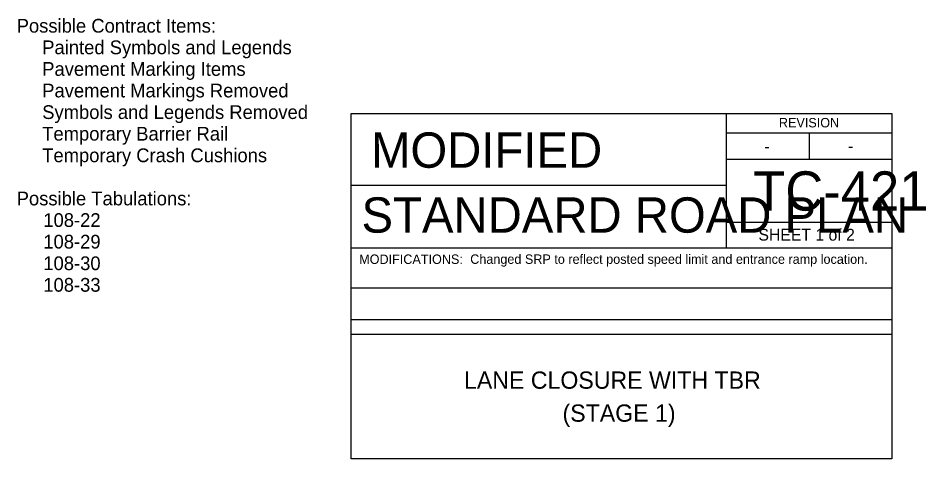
# Model space of a CAD drawing. Extents: x 10134 to 13311, y 7934 to 9733.
# Drawn here: x 12156 to 13311, y 7934 to 8495 of the extents above; entities that cross this region are included whole.
import ezdxf

# ---------------------------------------------------------------- set-up
doc = ezdxf.new("R2010")
doc.units = 0
for name, color, linetype in [('dsnStdBlock', 7, 'Continuous'), ('dsnStdBlockModified', 7, 'Continuous'), ('SheetText', 7, 'Continuous')]:
    doc.layers.add(name, color=color, linetype=linetype)

msp = doc.modelspace()

# ---------------------------------------------------------------- linework, layer by layer
at = {"layer": 'dsnStdBlock'}
for p, q in [((13056.6, 8374), (13056.6, 8282.7)), ((13056.6, 8349.1), (13267.5, 8349.1)), ((13162, 8349.1), (13162, 8315.9)), ((13056.6, 8315.9), (13267.5, 8315.9)), ((12579.5, 8282.7), (13056.6, 8282.7)), ((13056.6, 8282.7), (13056.6, 8202.7)), ((13267.5, 8234.9), (13056.6, 8234.9)), ((12579.5, 8202.7), (13267.5, 8202.7)), ((12579.5, 8151.7), (13267.5, 8151.7)), ((12579.5, 8111.7), (13267.5, 8111.7)), ((12579.5, 8092.7), (13267.5, 8092.7))]:
    msp.add_line(p, q, dxfattribs=at)
msp.add_lwpolyline([(12579.5, 8374), (13267.5, 8374), (13267.5, 7934), (12579.5, 7934)], close=True, dxfattribs=at)

# ---------------------------------------------------------------- texts
for s, height, p in [('REVISION', 12, (13123.6, 8356.2)), ('-', 15, (13105.1, 8324.6)), ('-', 15, (13211.6, 8325.1)), ('TC-421', 50, (13090.9, 8250.2)), ('STANDARD ROAD PLAN', 45.001, (12592.5, 8222.1)), ('SHEET 1 of 2', 15, (13097.6, 8212)), ('Changed SRP to reflect posted speed limit and entrance ramp location.', 12, (12730.8, 8182.4)), ('LANE CLOSURE WITH TBR', 22, (12722.9, 8023.3)), ('(STAGE 1)', 22, (12848.3, 7981.3))]:
    msp.add_text(s, height=height, dxfattribs=at).set_placement(p)
at = {"layer": 'dsnStdBlockModified'}
for s, height, p in [('MODIFIED', 45, (12604.6, 8304.8)), ('MODIFICATIONS:', 12, (12589.5, 8182.3))]:
    msp.add_text(s, height=height, dxfattribs=at).set_placement(p)
at = {"layer": 'SheetText'}
for s, p in [('Possible Contract Items:', (12153.7, 8476.9)), ('     Painted Symbols and Legends', (12153.7, 8449.4)), ('     Pavement Marking Items', (12153.7, 8421.9)), ('     Pavement Markings Removed', (12153.7, 8394.4)), ('     Symbols and Legends Removed', (12153.7, 8366.9)), ('     Temporary Barrier Rail', (12153.7, 8339.4)), ('     Temporary Crash Cushions', (12153.7, 8311.9)), ('Possible Tabulations:', (12153.7, 8256.9)), ('108-22', (12187.6, 8229.4)), ('108-29', (12187.6, 8201.9)), ('108-30', (12187.6, 8174.4)), ('108-33', (12187.6, 8146.9))]:
    msp.add_text(s, height=17.5, dxfattribs=at).set_placement(p)

doc.saveas('drawing.dxf')
